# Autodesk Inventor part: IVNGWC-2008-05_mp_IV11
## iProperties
Shininess: 64.0
Length Units: 11269
Angle Units: 11279
Time Units: 11290
Mass Units: 11283
Length Display Precision: 5
Angle Display Precision: 5
Compacted: True
Part Number: IVNGWC-2008-05_mp_IV11
Document SubType Name: Modeling
Created: 2008-05
Material: Standard
Designer: mp
Density: 0.0
Volumn: 0.0
Area: 0.0
PropertySet Name: Model Information
Control State: 0
Master: False
Checked Out: False
Author: mp
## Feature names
1. Sweeping1
